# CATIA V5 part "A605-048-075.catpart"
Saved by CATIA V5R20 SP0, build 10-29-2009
Part number: A605-048-075
Source: Unknown
Property "A": "0.000"
Property "ARTICLENO": "A605-048-075"
Property "BOMINFO": "A605-048-075"
Property "CODE": "A605-048-075"
Property "D": "9.000"
Property "FORM": "A"
Property "L": "75.000"
Property "L1": "45.000"
Property "LINA": "A605-048-075"
Property "NB": "A605-048-075"
Property "NBSYN": "$CODE."
Property "NN": "A605"
Property "NT": "Wear Plates, self-lubricating"
Property "SCREW": "2*M8X16"
Property "SUPPLIER": "CF"
Property "W": "48.000"
Bounding box of the stored display mesh (mm): x -48 to 0, y 0 to 5, z -75 to 0
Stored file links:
  C:\Users\Utente\Desktop\3D files A605\A605-048-075.catpart
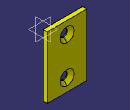
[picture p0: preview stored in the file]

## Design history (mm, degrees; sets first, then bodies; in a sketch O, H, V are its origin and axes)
Body1 "Geometry.1" (main body)
  Solid1 "A605-048-075.catpart": solid without history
